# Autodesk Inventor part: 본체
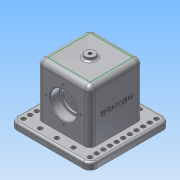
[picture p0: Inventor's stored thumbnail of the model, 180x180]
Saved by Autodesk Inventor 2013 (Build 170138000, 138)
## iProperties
Created: 2018-11
Part Number: 본체
Material: 알루미늄 6061
Document SubType Name: Modeling
Designer: Administrator
Density: 2.71 g/cm^3
Mass: 1022.46 g
Surface Area: 785.596 cm^2
Volume: 377.291 cm^3
Author: Administrator
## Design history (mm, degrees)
sketch "스케치2"
  geometry: L1 (-60, 60)-(60, 60); L2 (60, 60)-(60, -60); L3 (60, -60)-(-60, -60); L4 (-60, -60)-(-60, 60); 3 further points
  constraints: 8 end point, 2 midpoint, 2 parallel, 1 horizontal, 1 horizontal alignment, 1 perpendicular, 1 vertical alignment
  dimensions: "d0" = 120 distance of L1.start L1.end; "d2" = 120 distance of L1.end L2.end
extrude "돌출1" new body sketch "스케치2" distance "d3" = 10; taper "d4" = 0 deg
fillet "모깎기1" dims "d5" = 10
sketch "스케치5"
  geometry: L1 (-50, -60)-(50, -60) reference; L2 (60, -50)-(60, 50) reference; L3 (50, 60)-(-50, 60) reference; L4 (-60, 50)-(-60, -50) reference; L5 (-50, 50)-(-50, -50); L6 (-40, 50)-(-40, -50); L7 (-30, 50)-(-30, -50); L8 (-20, 50)-(-20, -50); L9 (-10, 50)-(-10, -50); L10 (0, 50)-(0, -50); L11 (10, 50)-(10, -50); L12 (20, 50)-(20, -50); L13 (30, 50)-(30, -50); L14 (40, 50)-(40, -50); L15 (-50, 50)-(50, 50); L16 (-50, 25)-(50, 25); L17 (-50, 0)-(50, 0); L18 (-50, -25)-(60, -25); L19 (-50, -50)-(50, -50); L20 (50, -50)-(50, 50); A1 r 10 centre (-50, 50) between (-50, 60) and (-60, 50) reference; A2 r 10 centre (-50, -50) between (-60, -50) and (-50, -60) reference; A3 r 10 centre (50, -50) between (50, -60) and (60, -50) reference; A4 r 10 centre (50, 50) between (60, 50) and (50, 60) reference; A5 r 10 centre (-50, 50) between (-50, 60) and (-60, 50) reference; 28 further points
  constraints: 32 end point, 26 coincident, 12 parallel, 5 point on line, 3 perpendicular, 2 midpoint
  dimensions: "d13" = 10 distance between parallel lines of L6 L5; "d15" = 10 distance between parallel lines of L7 L6; "d16" = 10 distance between parallel lines of L8 L7; "d17" = 10 distance between parallel lines of L8 L9; "d18" = 10 distance between parallel lines of L9 L10; "d19" = 10 distance between parallel lines of L11 L10; "d20" = 10 distance between parallel lines of L12 L11; "d21" = 10 distance between parallel lines of L13 L12; "d22" = 10 distance between parallel lines of L14 L13; "d23" = 25 distance between parallel lines of L16 L15; "d24" = 25 distance between parallel lines of L17 L16; "d25" = 25 distance between parallel lines of L18 L17
hole "구멍2" sketch "스케치5" diameter "d26" = 6.6; stored, may be unused: countersink angle "d30" = 90 deg, drill point angle "d32" = 0 deg; dims "d27" = 6, "d28" = 4, "d29" = 2, "d31" = 8
sketch "스케치6"
  geometry: L1 (-40, 40)-(40, 40); L2 (40, 40)-(40, -40); L3 (40, -40)-(-40, -40); L4 (-40, -40)-(-40, 40); 3 further points
  constraints: 8 end point, 2 midpoint, 2 parallel, 1 horizontal, 1 horizontal alignment, 1 perpendicular, 1 vertical alignment
  dimensions: "d33" = 80 distance of L1.start L1.end; "d35" = 80 distance of L3.end L1.start
extrude "돌출2" join sketch "스케치6" distance "d36" = 80; taper "d37" = 0 deg
fillet "모깎기2" dims "d38" = 8
fillet "모깎기3" dims "d39" = 8
sketch "스케치7"
  geometry: L1 (-23, 30)-(23, 30); L2 (23, 30)-(23, -30); L3 (23, -30)-(-23, -30); L4 (-23, -30)-(-23, 30); 3 further points
  constraints: 8 end point, 2 midpoint, 2 parallel, 1 horizontal, 1 horizontal alignment, 1 perpendicular, 1 vertical alignment
  dimensions: "d40" = 46 distance of L1.start L1.end; "d42" = 60 distance of L1.end L2.end
extrude "돌출3" cut sketch "스케치7" distance "d43" = 80; taper "d44" = 0 deg
fillet "모깎기4" dims "d45" = 3
sketch "스케치8"
  geometry: L1 (-67.73, 48)-(73.619, 48); L2 (-50, 0)-(50, 0) reference; L3 (-40, 10)-(-40, 82) reference; L4 (-40, 68)-(-26, 68); L5 (-26, 68)-(-26, 64.5); L6 (-26, 64.5)-(26, 64.5); L7 (26, 64.5)-(26, 68); L8 (26, 68)-(40, 68); L9 (40, 82)-(40, 10) reference; L10 (40, 48)-(-40, 48); L11 (-40, 68)-(-40, 48); L12 (40, 68)-(40, 48); L13 (-23, 77)-(-23, 0) reference; L14 (23, 0)-(23, 77) reference; 1 further point
  constraints: 18 end point, 6 point on line, 3 perpendicular, 2 collinear, 2 parallel, 1 horizontal
  dimensions: "d46" = 48 distance between parallel lines of L2 L1; "d47" = 16.5 distance between parallel lines of L10 L6; "d48" = 40 diameter of L4 L1; "d50" = 40 diameter of L8 L1; "d52" = 3 distance between parallel lines of L13 L5; "d53" = 3 distance between parallel lines of L14 L7
revolve "회전1" sketch "스케치8" stored, may be unused: angle "d51" = 90 deg
fillet "모깎기5" dims "d54" = 0.6
chamfer "모따기1" distance "d55" = 1; stored, may be unused: second distance "d56" = 2, angle "d57" = 45 deg
sketch "스케치12"
  geometry: L1 (-32, 32)-(32, 32) reference; L2 (-32, -32)-(-32, 32) reference; L3 (32, -32)-(-32, -32) reference; L4 (32, 32)-(32, -32) reference; 1 further point
sketch "스케치13"
  geometry: L1 (32, 32)-(32, -32) reference; L2 (0, 0)-(0, 52.14); L3 (0, 0)-(0, 0); C1 r 7.5 at (0, 0)
  constraints: 4 end point, 1 centre point, 1 coincident, 1 parallel, 1 perpendicular, 1 vertical alignment
  dimensions: "d58" = 15 diameter of C1
extrude "돌출4" join sketch "스케치13" distance "d60" = 5; taper "d61" = 0 deg
fillet "모깎기6" dims "d62" = 3
sketch "스케치14"
  geometry: C1 r 7.5 at (0, 0) reference; 1 further point
  constraints: 1 coincident
hole "구멍3" sketch "스케치14" at (0, 0) diameter "d63" = 4.917; stored, may be unused: countersink angle "d67" = 90 deg, drill point angle "d69" = 0 deg; dims "d64" = 18, "d65" = 4, "d66" = 2, "d68" = 20
sketch "스케치15" dims "d70" = 52
  geometry: L1 (72, 0)-(0, 0) reference; L2 (38, 32)-(38, 32); L3 (38, 32)-(38, 104.713); C1 r 21 at (38, 32) reference; 3 further points
  constraints: 4 end point, 2 vertical alignment, 1 coincident, 1 parallel, 1 perpendicular, 1 point on line, 2 other
hole "구멍4" sketch "스케치15" at (38, 58) diameter "d72" = 3.242; stored, may be unused: countersink angle "d76" = 90 deg, drill point angle "d78" = 118 deg; dims "d73" = 8, "d74" = 4, "d75" = 2, "d77" = 10
sketch "스케치16"
  geometry: L1 (82, -10)-(-18, -10) reference; 3 further points
  constraints: 1 midpoint, 1 vertical alignment, 1 other
  dimensions: "d82" = 48 distance from line of L1 point (32, 38)
extrude "돌출5" join sketch "스케치16" distance "d83" = 0.5; taper "d84" = 0 deg
fillet "모깎기7" dims "d85" = 3
node "솔리드1"
pattern_circular "원형 패턴1" dims angle "d80" = 360 deg
mirror "대칭1"
node "투영된 루프1"
